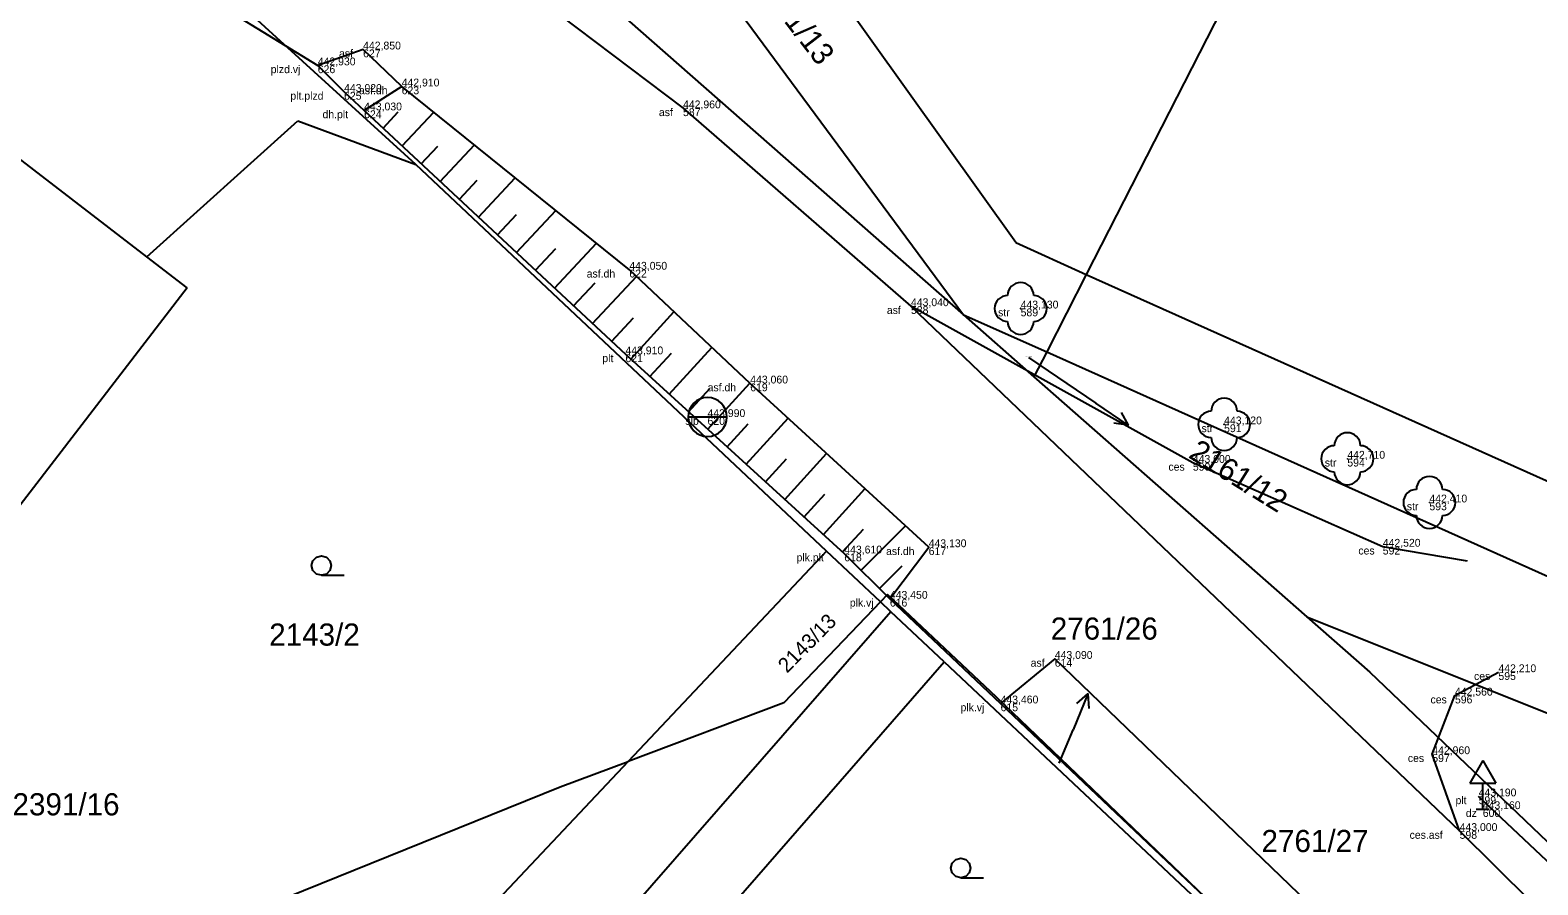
# Model space of a CAD drawing. Extents: x -747792 to -745414, y -1093712 to -1091463.
# Drawn here: x -746639.4 to -746581.5, y -1093180.1 to -1093147.3 of the extents above; entities that cross this region are included whole.
import ezdxf

# ---------------------------------------------------------------- set-up
doc = ezdxf.new("R2010")
doc.units = 0
for name, color, linetype in [('Budovy', 7, 'Continuous'), ('Doplňkové značky', 7, 'Continuous'), ('Hladina', 7, 'Continuous'), ('Koleje_dopravní prvky', 7, 'Continuous'), ('Kultury', 7, 'Continuous'), ('Nezařazené objekty', 7, 'Continuous'), ('Nivelační značky_hrany', 7, 'Continuous'), ('Názvy obcí_ulic', 7, 'Continuous'), ('Pracovní_bod JDTM STC_VC - výška', 7, 'Continuous'), ('Pracovní_bod PPBP', 7, 'Continuous'), ('Pracovní_bod PPBP - výška', 7, 'Continuous'), ('Rozhraní ploch', 7, 'Continuous'), ('Stromy_porost', 7, 'Continuous'), ('Výškopis', 7, 'Continuous'), ('Čísla popisná_parcelní', 7, 'Continuous')]:
    doc.layers.add(name, color=color, linetype=linetype)

msp = doc.modelspace()

# ---------------------------------------------------------------- linework, layer by layer
at = {"layer": 'Budovy'}
for points in [[(-746628.21, -1093168.24), (-746628.4, -1093168.19), (-746628.535, -1093168.05), (-746628.585, -1093167.865), (-746628.535, -1093167.68), (-746628.4, -1093167.54), (-746628.21, -1093167.49), (-746628.02, -1093167.54), (-746627.885, -1093167.68), (-746627.835, -1093167.865), (-746627.885, -1093168.05), (-746628.02, -1093168.19), (-746628.21, -1093168.24), (-746627.335, -1093168.24)], [(-746603.67, -1093179.86), (-746603.86, -1093179.81), (-746603.995, -1093179.67), (-746604.045, -1093179.485), (-746603.995, -1093179.3), (-746603.86, -1093179.16), (-746603.67, -1093179.11), (-746603.48, -1093179.16), (-746603.345, -1093179.3), (-746603.295, -1093179.485), (-746603.345, -1093179.67), (-746603.48, -1093179.81), (-746603.67, -1093179.86), (-746602.795, -1093179.86)]]:
    msp.add_lwpolyline(points, dxfattribs=at)
at = {"layer": 'Doplňkové značky'}
for points in [[(-746601.07, -1093159.87), (-746598.48, -1093161.63)], [(-746597.239, -1093162.472), (-746598.48, -1093161.63)], [(-746597.512, -1093161.985), (-746597.239, -1093162.472), (-746597.793, -1093162.398)], [(-746598.787, -1093172.794), (-746599.36, -1093174.18)], [(-746599.209, -1093173.16), (-746598.787, -1093172.794), (-746598.747, -1093173.351)], [(-746599.89, -1093175.46), (-746599.36, -1093174.18)]]:
    msp.add_lwpolyline(points, dxfattribs=at)
at = {"layer": 'Hladina'}
for p, q in [((-746626.61, -1093148.04), (-746626.61, -1093148.04)), ((-746628.35, -1093148.65), (-746628.35, -1093148.65)), ((-746625.13, -1093149.46), (-746625.13, -1093149.46)), ((-746627.34, -1093149.67), (-746627.34, -1093149.67)), ((-746626.57, -1093150.38), (-746626.57, -1093150.38)), ((-746614.33, -1093150.3), (-746614.33, -1093150.3)), ((-746616.39, -1093156.5), (-746616.39, -1093156.5)), ((-746605.58, -1093157.9), (-746605.58, -1093157.9)), ((-746601.37, -1093157.99), (-746601.37, -1093157.99)), ((-746616.54, -1093159.75), (-746616.54, -1093159.75)), ((-746611.75, -1093160.87), (-746611.75, -1093160.87)), ((-746613.39, -1093162.16), (-746613.39, -1093162.16)), ((-746593.56, -1093162.44), (-746593.56, -1093162.44)), ((-746594.76, -1093163.92), (-746594.76, -1093163.92)), ((-746588.83, -1093163.76), (-746588.83, -1093163.76)), ((-746585.68, -1093165.44), (-746585.68, -1093165.44)), ((-746608.14, -1093167.4), (-746608.14, -1093167.4)), ((-746604.9, -1093167.16), (-746604.9, -1093167.16)), ((-746587.47, -1093167.14), (-746587.47, -1093167.14)), ((-746606.39, -1093169.14), (-746606.39, -1093169.14)), ((-746600.06, -1093171.45), (-746600.06, -1093171.45)), ((-746583.03, -1093171.96), (-746583.03, -1093171.96)), ((-746602.14, -1093173.16), (-746602.14, -1093173.16)), ((-746584.7, -1093172.86), (-746584.7, -1093172.86)), ((-746585.57, -1093175.11), (-746585.57, -1093175.11)), ((-746583.79, -1093176.73), (-746583.79, -1093176.73)), ((-746583.63, -1093177.22), (-746583.63, -1093177.22)), ((-746584.52, -1093178.06), (-746584.52, -1093178.06))]:
    msp.add_line(p, q, dxfattribs=at)
at = {"layer": 'Kultury'}
msp.add_lwpolyline([(-746634.91, -1093156), (-746642.16, -1093150.44)], dxfattribs=at)
at = {"layer": 'Nezařazené objekty'}
for points in [[(-746628.35, -1093148.65), (-746627.34, -1093149.67)], [(-746627.34, -1093149.67), (-746626.57, -1093150.38), (-746616.54, -1093159.75), (-746608.14, -1093167.4), (-746606.39, -1093169.14)], [(-746602.14, -1093173.16), (-746591.1, -1093183.64)], [(-746567.68, -1093191.92), (-746583.79, -1093176.73)]]:
    msp.add_lwpolyline(points, dxfattribs=at)
at = {"layer": 'Nivelační značky_hrany'}
for points in [[(-746621.78, -1093144.65), (-746614.33, -1093150.3), (-746605.58, -1093157.9), (-746584.52, -1093178.06), (-746562.55, -1093199.83)], [(-746584.22, -1093167.7), (-746587.47, -1093167.14), (-746594.76, -1093163.92), (-746605.58, -1093157.9)], [(-746591.1, -1093183.64), (-746589.66, -1093181.47), (-746600.06, -1093171.45), (-746602.14, -1093173.16)], [(-746584.52, -1093178.06), (-746585.57, -1093175.11), (-746584.7, -1093172.86), (-746583.03, -1093171.96)]]:
    msp.add_lwpolyline(points, dxfattribs=at)
at = {"layer": 'Názvy obcí_ulic'}
for p, q in [((-746583.63, -1093175.354), (-746584.13, -1093176.22)), ((-746583.63, -1093175.354), (-746583.13, -1093176.22)), ((-746584.13, -1093176.22), (-746583.13, -1093176.22)), ((-746583.63, -1093177.22), (-746583.63, -1093176.22)), ((-746583.88, -1093177.22), (-746583.38, -1093177.22))]:
    msp.add_line(p, q, dxfattribs=at)
at = {"layer": 'Pracovní_bod JDTM STC_VC - výška'}
for centre in [(-746601.37, -1093157.99), (-746593.56, -1093162.44), (-746588.83, -1093163.76), (-746585.68, -1093165.44)]:
    msp.add_circle(centre, 0.0005, dxfattribs=at)
for centre, start, end in [((-746601.37, -1093157.49), 0, 179.99999), ((-746601.87, -1093157.99), 89.99999, 269.99999), ((-746600.87, -1093157.99), 270, 89.99999), ((-746601.37, -1093158.49), 179.99999, 359.99999), ((-746593.56, -1093161.94), 0, 179.99999), ((-746594.06, -1093162.44), 89.99999, 269.99999), ((-746593.06, -1093162.44), 270, 89.99999), ((-746588.83, -1093163.26), 0, 179.99999), ((-746593.56, -1093162.94), 179.99999, 359.99999), ((-746589.33, -1093163.76), 89.99999, 269.99999), ((-746588.33, -1093163.76), 270, 89.99999), ((-746588.83, -1093164.26), 179.99999, 359.99999), ((-746585.68, -1093164.94), 0, 179.99999), ((-746586.18, -1093165.44), 89.99999, 269.99999), ((-746585.18, -1093165.44), 270, 89.99999), ((-746585.68, -1093165.94), 179.99999, 359.99999)]:
    msp.add_arc(centre, 0.5, start, end, dxfattribs=at)
at = {"layer": 'Pracovní_bod PPBP'}
for points in [[(-746606.39, -1093169.14), (-746604.9, -1093167.16), (-746611.75, -1093160.87), (-746616.39, -1093156.5), (-746625.13, -1093149.46), (-746626.61, -1093148.04), (-746628.35, -1093148.65)], [(-746625.13, -1093149.46), (-746626.57, -1093150.38)], [(-746625.839, -1093151.063), (-746625.26, -1093150.442)], [(-746625.109, -1093151.745), (-746623.9, -1093150.451)], [(-746624.378, -1093152.428), (-746623.748, -1093151.754)], [(-746623.647, -1093153.111), (-746622.338, -1093151.709)], [(-746622.186, -1093154.476), (-746620.776, -1093152.967)], [(-746622.916, -1093153.793), (-746622.237, -1093153.066)], [(-746621.455, -1093155.159), (-746620.725, -1093154.377)], [(-746620.724, -1093155.841), (-746619.214, -1093154.225)], [(-746619.993, -1093156.524), (-746619.213, -1093155.689)], [(-746619.263, -1093157.207), (-746617.653, -1093155.483)], [(-746618.532, -1093157.889), (-746617.702, -1093157.001)], [(-746617.801, -1093158.572), (-746616.111, -1093156.763)], [(-746616.337, -1093159.935), (-746614.678, -1093158.113)], [(-746617.07, -1093159.255), (-746616.227, -1093158.351)], [(-746615.598, -1093160.608), (-746614.774, -1093159.703)], [(-746614.859, -1093161.281), (-746613.222, -1093159.484)], [(-746614.119, -1093161.955), (-746613.306, -1093161.062)], [(-746613.38, -1093162.628), (-746611.766, -1093160.855)], [(-746611.901, -1093163.975), (-746610.293, -1093162.208)], [(-746612.641, -1093163.301), (-746611.835, -1093162.417)], [(-746611.162, -1093164.648), (-746610.359, -1093163.766)], [(-746610.423, -1093165.321), (-746608.819, -1093163.561)], [(-746609.683, -1093165.995), (-746608.883, -1093165.116)], [(-746608.944, -1093166.668), (-746607.346, -1093164.914)], [(-746608.205, -1093167.341), (-746607.407, -1093166.466)], [(-746607.493, -1093168.044), (-746605.796, -1093166.337)], [(-746606.784, -1093168.749), (-746605.921, -1093167.881)]]:
    msp.add_lwpolyline(points, dxfattribs=at)
at = {"layer": 'Pracovní_bod PPBP - výška'}
for points in [[(-746633.66, -1093145.39), (-746628.35, -1093148.65)], [(-746606.39, -1093169.14), (-746602.14, -1093173.16)]]:
    msp.add_lwpolyline(points, dxfattribs=at)
at = {"layer": 'Stromy_porost'}
for points in [[(-746601.56, -1093155.45), (-746618.27, -1093132.06)], [(-746619.59, -1093136.52), (-746603.57, -1093158.23)], [(-746621.42, -1093142.52), (-746603.57, -1093158.23)], [(-746591.61, -1093142.5), (-746598.85, -1093156.69)], [(-746624.59, -1093152.46), (-746632.83, -1093144.93)], [(-746634.91, -1093156), (-746629.11, -1093150.78)], [(-746629.11, -1093150.78), (-746624.59, -1093152.46)], [(-746608.82, -1093167.31), (-746624.59, -1093152.46)], [(-746601.56, -1093155.45), (-746598.85, -1093156.69)], [(-746633.36, -1093157.2), (-746634.91, -1093156)], [(-746598.85, -1093156.69), (-746600.37, -1093159.66)], [(-746598.85, -1093156.69), (-746568.46, -1093170.31)], [(-746633.36, -1093157.2), (-746648.65, -1093177.1)], [(-746603.57, -1093158.23), (-746600.37, -1093159.66)], [(-746603.57, -1093158.23), (-746600.86, -1093160.62)], [(-746600.37, -1093159.66), (-746600.86, -1093160.62)], [(-746600.37, -1093159.66), (-746567.68, -1093174.32)], [(-746600.86, -1093160.62), (-746590.38, -1093169.84)], [(-746608.82, -1093167.31), (-746616.43, -1093175.39)], [(-746606.75, -1093169.26), (-746608.82, -1093167.31)], [(-746606.48, -1093168.98), (-746606.75, -1093169.26)], [(-746602.3, -1093172.92), (-746606.48, -1093168.98)], [(-746606.35, -1093169.64), (-746616.32, -1093181.06)], [(-746606.75, -1093169.26), (-746610.46, -1093173.14)], [(-746606.35, -1093169.64), (-746606.75, -1093169.26)], [(-746604.31, -1093171.56), (-746606.35, -1093169.64)], [(-746590.38, -1093169.84), (-746570.5, -1093177.8)], [(-746590.38, -1093169.84), (-746587.97, -1093171.96)], [(-746613.51, -1093182.12), (-746604.31, -1093171.56)], [(-746604.31, -1093171.56), (-746593.53, -1093181.7)], [(-746587.97, -1093171.96), (-746563.01, -1093195.81)], [(-746610.46, -1093173.14), (-746616.43, -1093175.39)], [(-746593.35, -1093181.5), (-746602.3, -1093172.92)], [(-746616.43, -1093175.39), (-746625.58, -1093185.11)], [(-746619.04, -1093176.37), (-746616.43, -1093175.39)], [(-746630.23, -1093180.88), (-746619.04, -1093176.37)]]:
    msp.add_lwpolyline(points, dxfattribs=at)
at = {"layer": 'Čísla popisná_parcelní'}
msp.add_line((-746612.642, -1093162.16), (-746614.138, -1093162.16), dxfattribs=at)
for start, end in [(0, 180), (180, 0)]:
    msp.add_arc((-746613.39, -1093162.16), 0.747, start, end, dxfattribs=at)

# ---------------------------------------------------------------- texts
at = {"layer": 'Doplňkové značky'}
msp.add_text('2161/12', height=0.85, rotation=328.13293, dxfattribs=at).set_placement((-746594.969, -1093163.692))
for s, p in [('2761/26', (-746600.215, -1093170.71)), ('2391/16', (-746640.068, -1093177.46)), ('2761/27', (-746592.125, -1093178.87))]:
    msp.add_text(s, height=0.85, dxfattribs=at).set_placement(p)
at = {"layer": 'Koleje_dopravní prvky'}
for s, height, rotation, p in [('2161/13', 0.85, 307.62104, (-746611.639, -1093145.454)), ('2143/13', 0.57, 45.32096, (-746610.339, -1093172.02))]:
    msp.add_text(s, height=height, rotation=rotation, dxfattribs=at).set_placement(p)
for s, height, p in [('2161/12', 0.05, (-746601.185, -1093159.87)), ('2143/2', 0.85, (-746630.214, -1093170.94)), ('2761/26', 0.05, (-746599.89, -1093175.46))]:
    msp.add_text(s, height=height, dxfattribs=at).set_placement(p)
at = {"layer": 'Rozhraní ploch'}
for s, p in [(' asf', (-746627.647, -1093148.34)), ('627', (-746626.61, -1093148.34)), (' plzd.vj', (-746630.268, -1093148.95)), ('626', (-746628.35, -1093148.95)), (' asf.dh', (-746626.878, -1093149.76)), ('623', (-746625.13, -1093149.76)), (' plt.plzd', (-746629.513, -1093149.97)), ('625', (-746627.34, -1093149.97)), (' dh.plt', (-746628.28, -1093150.68)), ('624', (-746626.57, -1093150.68)), (' asf', (-746615.367, -1093150.6)), ('587', (-746614.33, -1093150.6)), (' asf.dh', (-746618.138, -1093156.8)), ('622', (-746616.39, -1093156.8)), (' asf', (-746606.617, -1093158.2)), ('588', (-746605.58, -1093158.2)), (' str', (-746602.348, -1093158.29)), ('589', (-746601.37, -1093158.29)), (' plt', (-746617.539, -1093160.05)), ('621', (-746616.54, -1093160.05)), (' asf.dh', (-746613.498, -1093161.17)), ('619', (-746611.75, -1093161.17)), (' slb', (-746614.351, -1093162.46)), ('620', (-746613.39, -1093162.46)), (' str', (-746594.538, -1093162.74)), ('591', (-746593.56, -1093162.74)), ('590', (-746594.76, -1093164.22)), (' str', (-746589.808, -1093164.06)), ('594', (-746588.83, -1093164.06)), (' ces', (-746595.809, -1093164.22)), (' str', (-746586.658, -1093165.74)), ('593', (-746585.68, -1093165.74)), (' plk.plt', (-746610.084, -1093167.7)), ('618', (-746608.14, -1093167.7)), (' asf.dh', (-746606.648, -1093167.46)), ('617', (-746604.9, -1093167.46)), (' ces', (-746588.519, -1093167.44)), ('592', (-746587.47, -1093167.44)), (' plk.vj', (-746608.039, -1093169.44)), ('616', (-746606.39, -1093169.44)), (' asf', (-746601.097, -1093171.75)), ('614', (-746600.06, -1093171.75)), (' ces', (-746584.079, -1093172.26)), ('595', (-746583.03, -1093172.26)), (' plk.vj', (-746603.789, -1093173.46)), ('615', (-746602.14, -1093173.46)), (' ces', (-746585.749, -1093173.16)), ('596', (-746584.7, -1093173.16)), (' ces', (-746586.619, -1093175.41)), ('597', (-746585.57, -1093175.41)), (' plt', (-746584.789, -1093177.03)), (' dz', (-746584.395, -1093177.52)), ('599', (-746583.79, -1093177.03)), ('600', (-746583.63, -1093177.52)), (' ces.asf', (-746586.551, -1093178.36)), ('598', (-746584.52, -1093178.36))]:
    msp.add_text(s, height=0.3, dxfattribs=at).set_placement(p)
at = {"layer": 'Výškopis'}
for s, p in [('442,850', (-746626.61, -1093148.04)), ('442,930', (-746628.35, -1093148.65)), ('443,020', (-746627.34, -1093149.67)), ('442,910', (-746625.13, -1093149.46)), ('442,960', (-746614.33, -1093150.3)), ('443,030', (-746626.57, -1093150.38)), ('443,050', (-746616.39, -1093156.5)), ('443,040', (-746605.58, -1093157.9)), ('443,130', (-746601.37, -1093157.99)), ('443,910', (-746616.54, -1093159.75)), ('443,060', (-746611.75, -1093160.87)), ('443,990', (-746613.39, -1093162.16)), ('443,120', (-746593.56, -1093162.44)), ('443,000', (-746594.76, -1093163.92)), ('442,710', (-746588.83, -1093163.76)), ('442,410', (-746585.68, -1093165.44)), ('443,130', (-746604.9, -1093167.16)), ('442,520', (-746587.47, -1093167.14)), ('443,610', (-746608.14, -1093167.4)), ('443,450', (-746606.39, -1093169.14)), ('443,090', (-746600.06, -1093171.45)), ('442,210', (-746583.03, -1093171.96)), ('442,560', (-746584.7, -1093172.86)), ('443,460', (-746602.14, -1093173.16)), ('442,960', (-746585.57, -1093175.11)), ('443,190', (-746583.79, -1093176.73)), ('443,160', (-746583.63, -1093177.22)), ('443,000', (-746584.52, -1093178.06))]:
    msp.add_text(s, height=0.3, dxfattribs=at).set_placement(p)

doc.saveas('drawing.dxf')
